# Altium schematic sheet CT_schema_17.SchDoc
size 742 x 377 mm
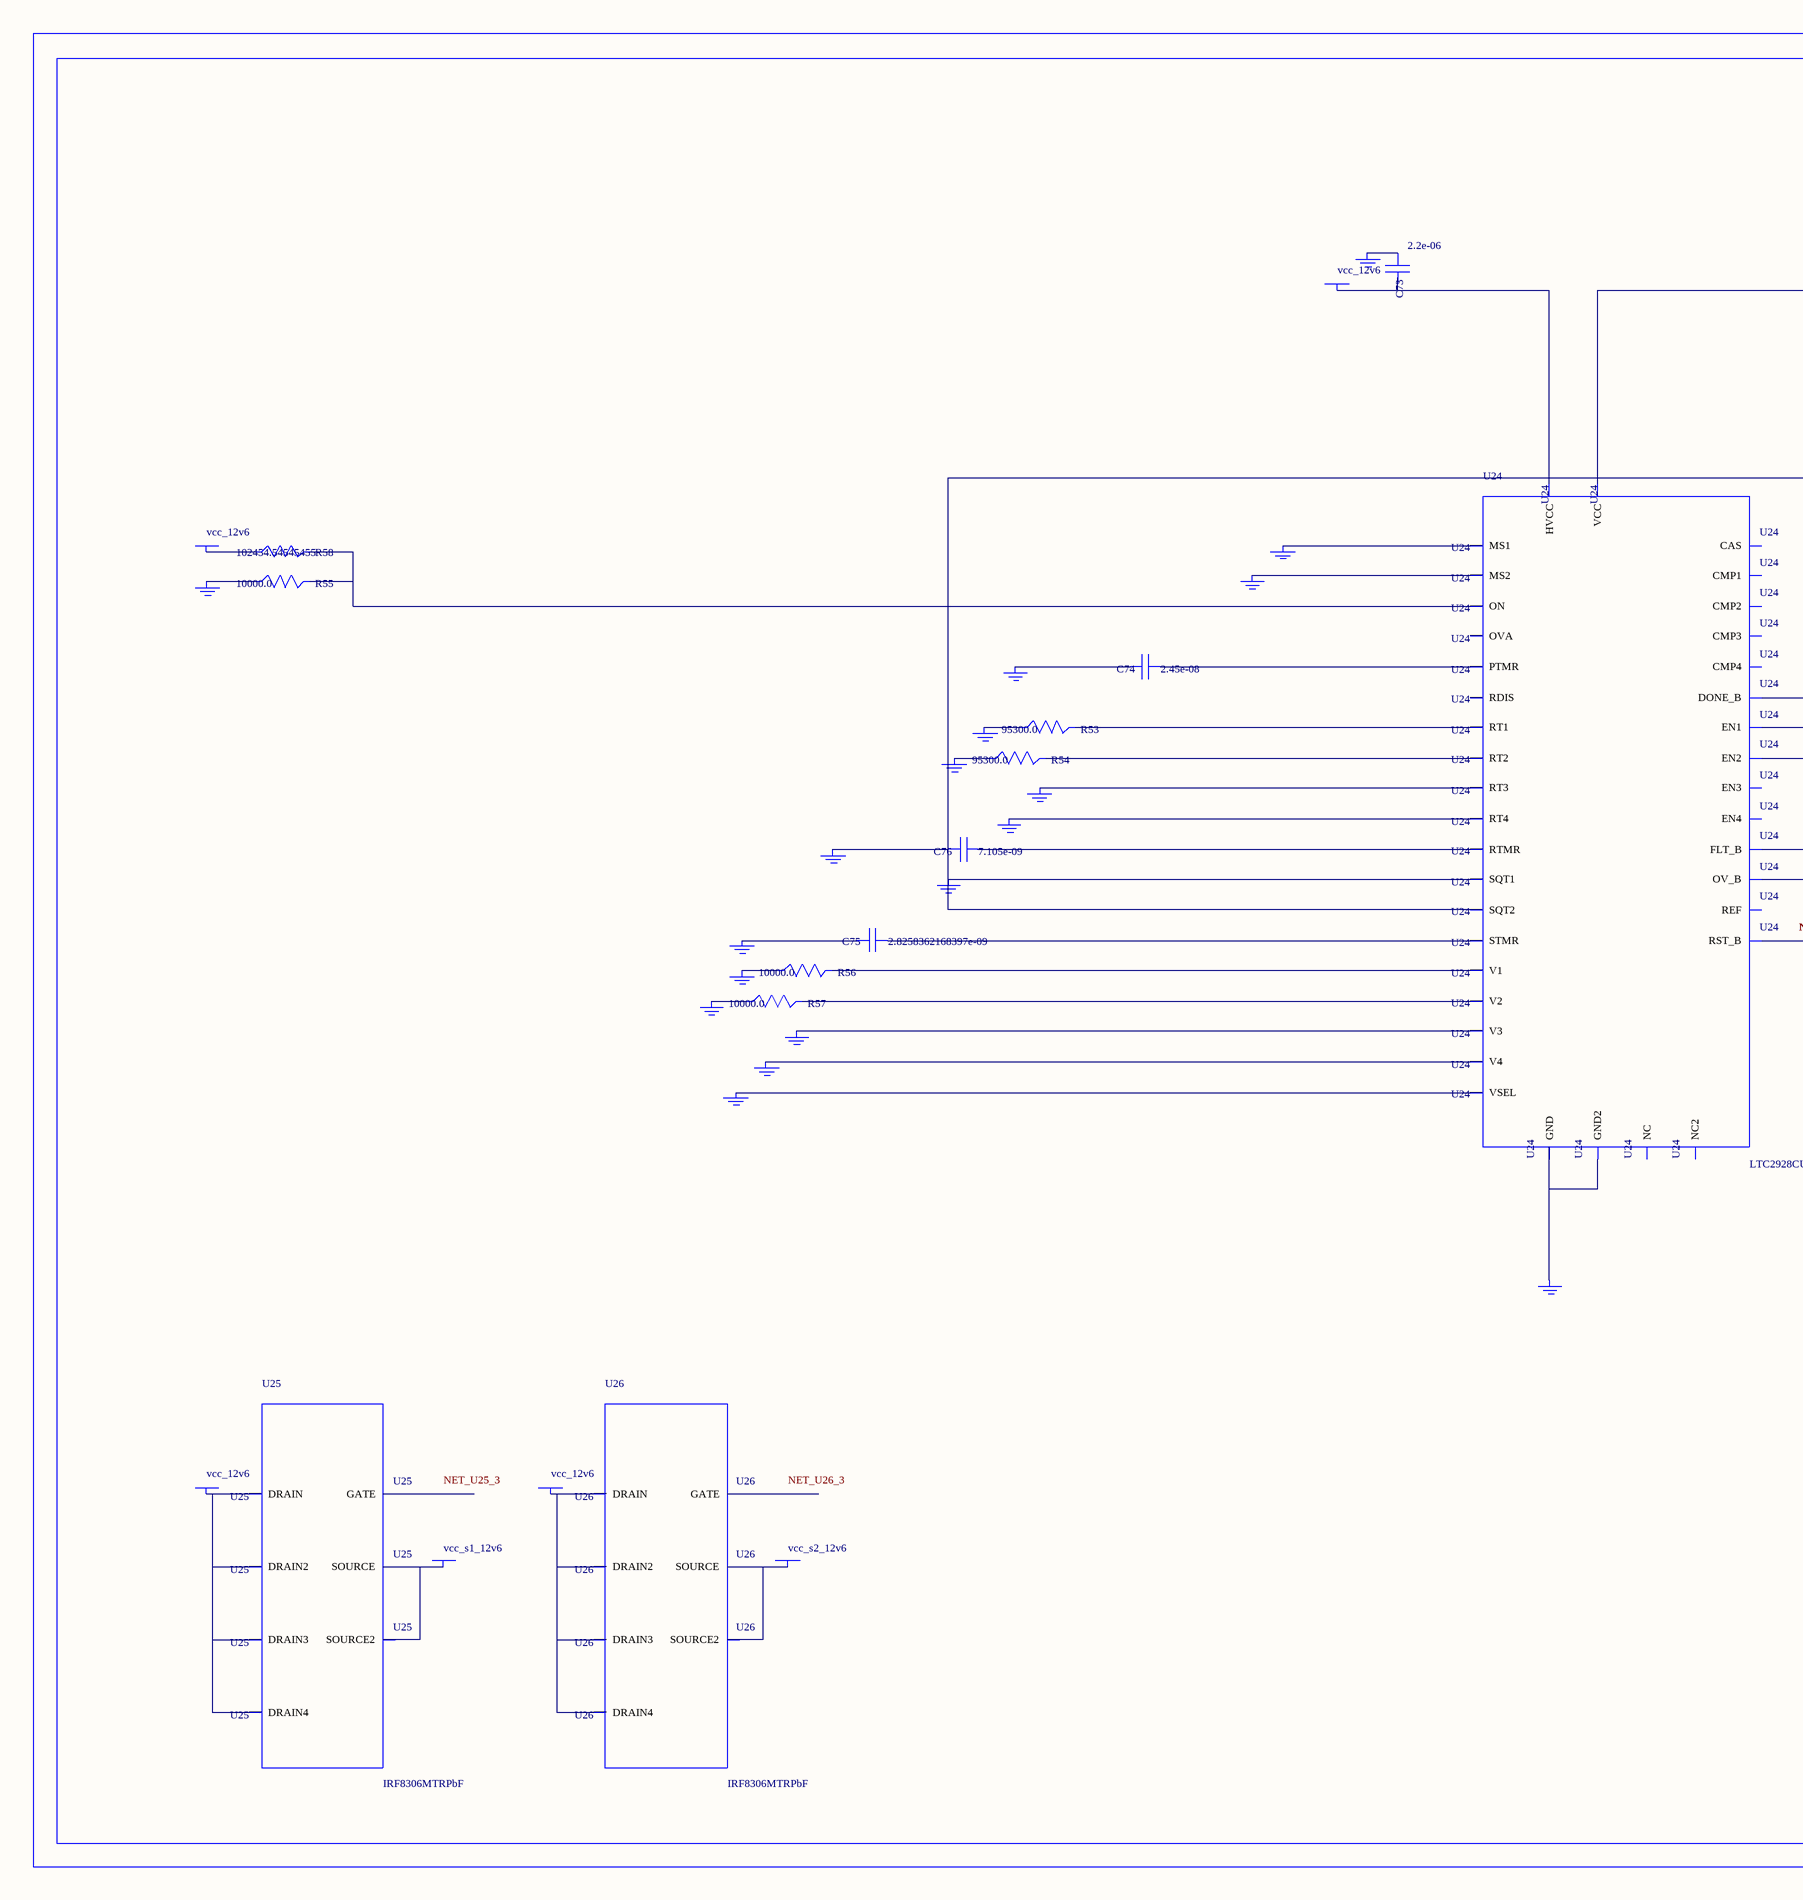
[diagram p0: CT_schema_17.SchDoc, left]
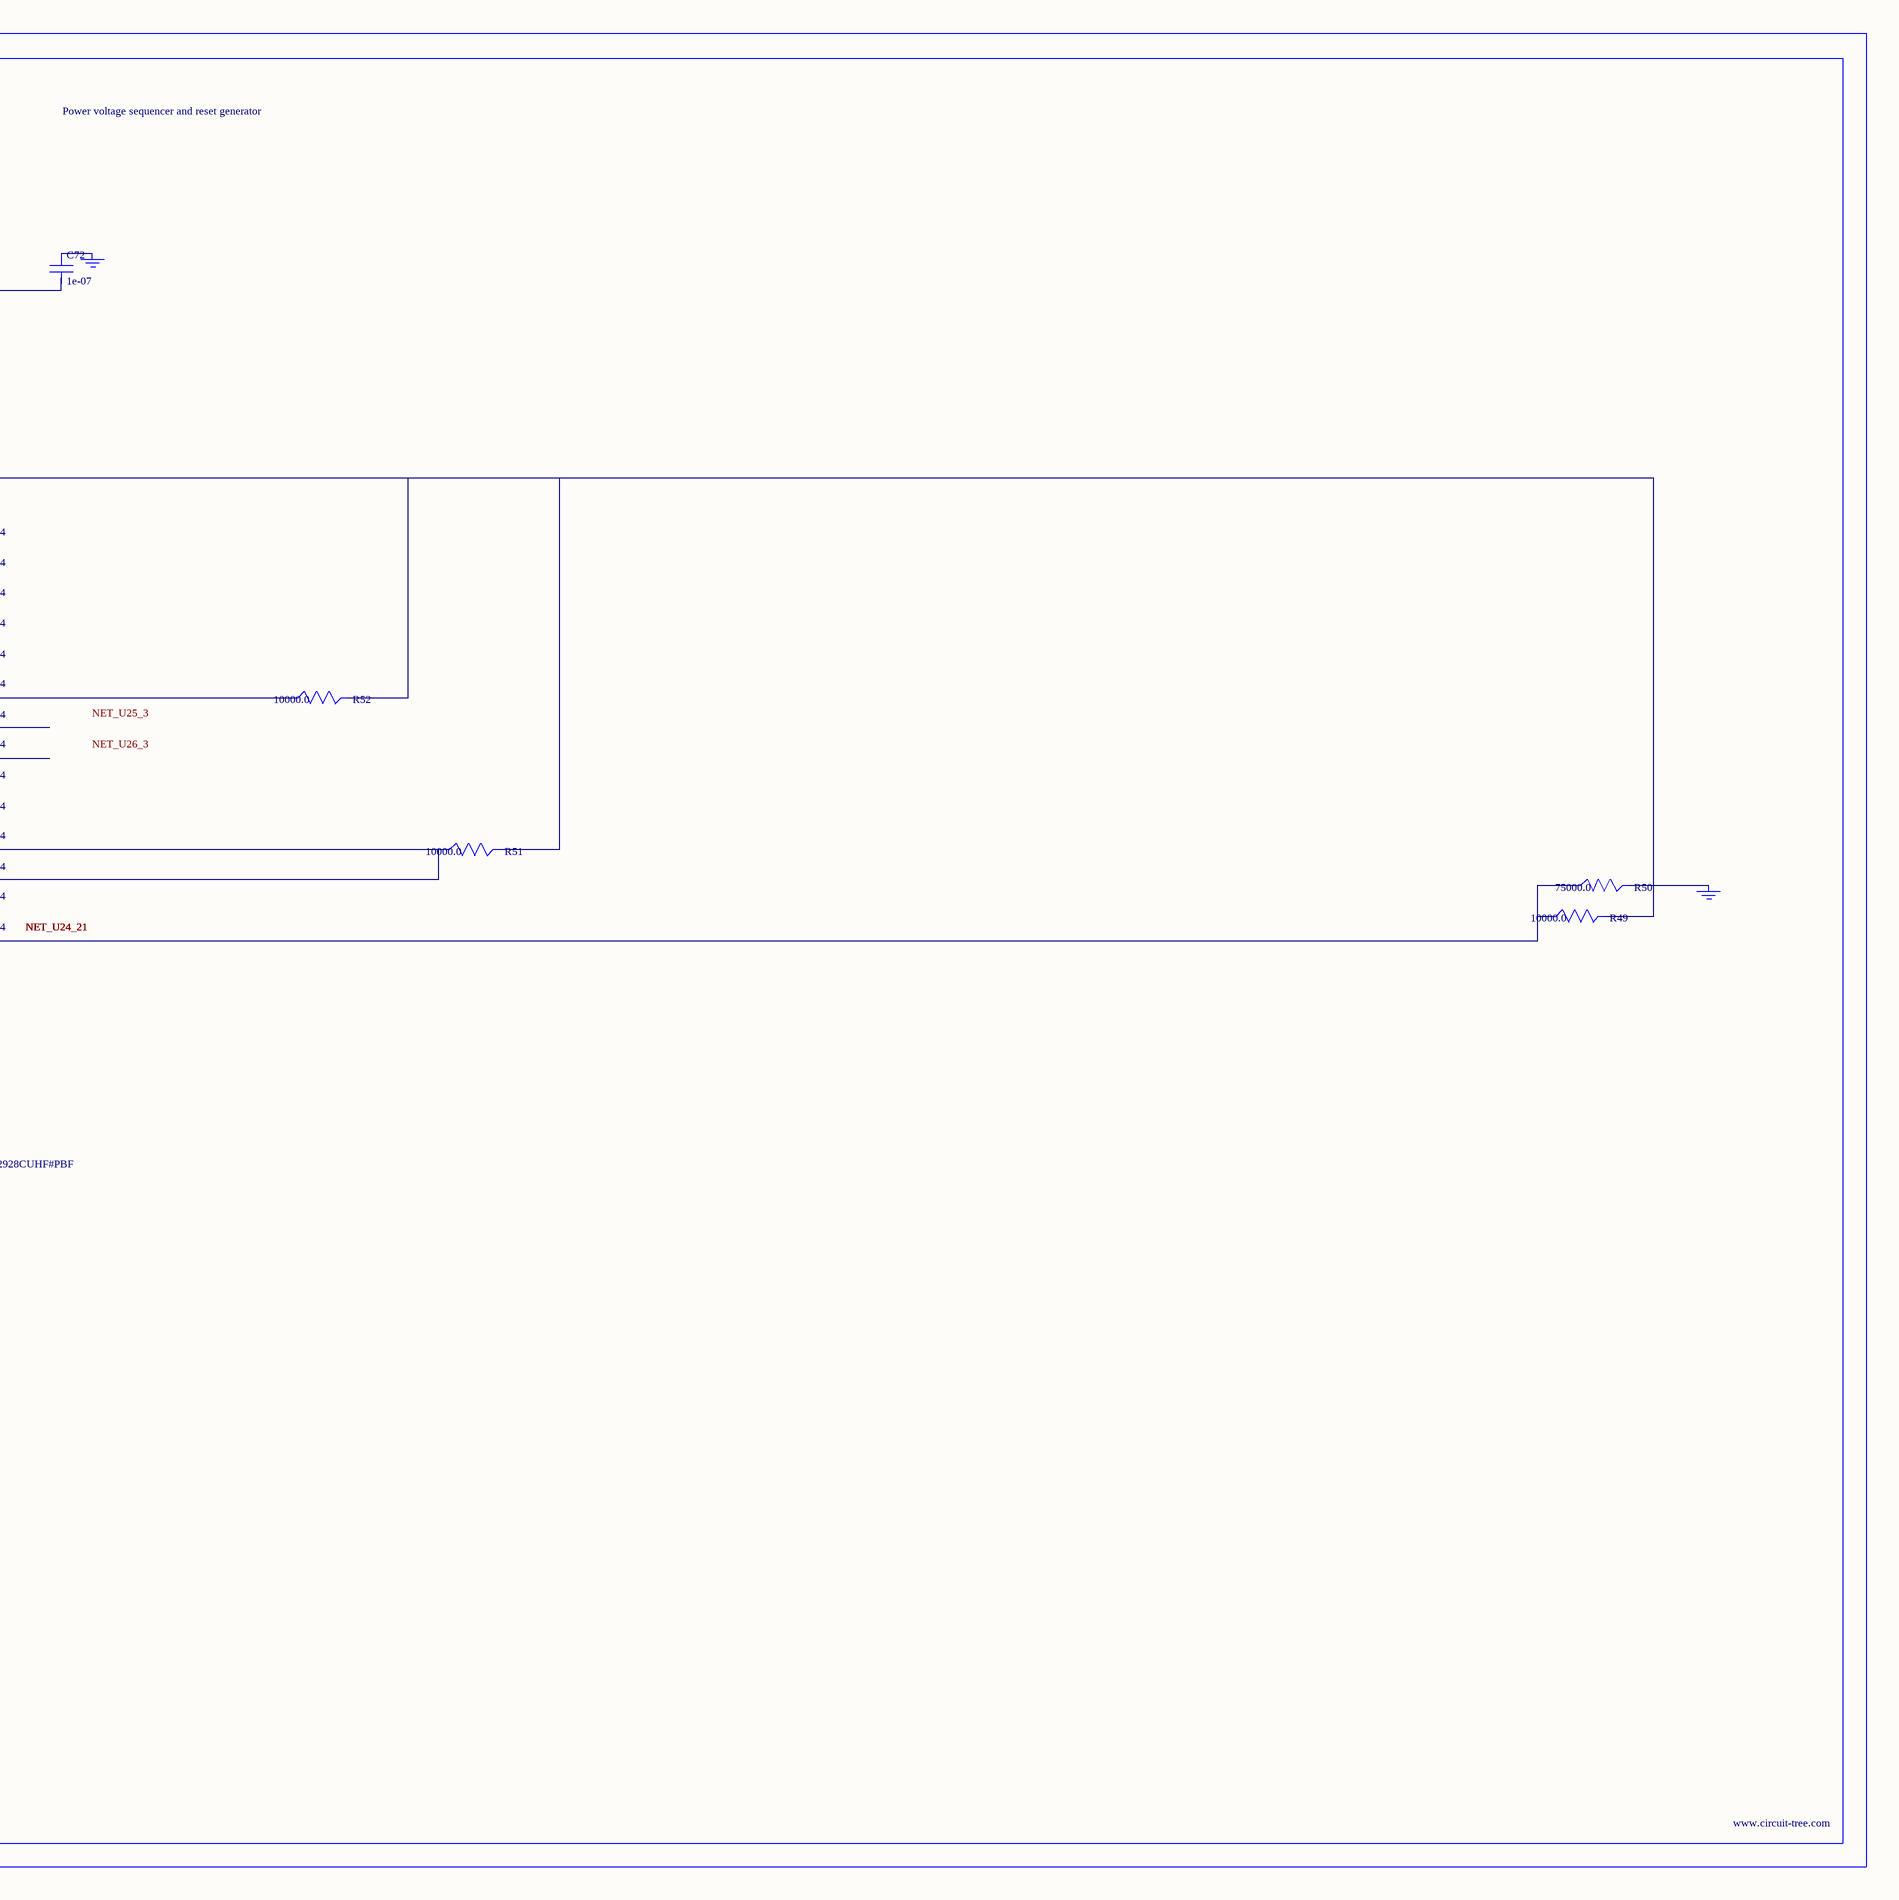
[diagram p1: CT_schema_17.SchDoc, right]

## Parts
BORDER16  (no value)
C72  1e-07  [C0402]
C73  2.2e-06  [C0603]
C74  2.45e-08  [R0603]
C75  2.8258362168397e-09  [R0603]
C76  7.105e-09  [R0603]
GND_INSTANCE_16_0  (no value)
GND_INSTANCE_16_1  (no value)
GND_INSTANCE_16_2  (no value)
GND_INSTANCE_16_3  (no value)
GND_INSTANCE_16_4  (no value)
GND_INSTANCE_16_5  (no value)
GND_INSTANCE_16_6  (no value)
GND_INSTANCE_16_7  (no value)
GND_INSTANCE_16_8  (no value)
GND_INSTANCE_16_9  (no value)
GND_INSTANCE_16_10  (no value)
GND_INSTANCE_16_11  (no value)
GND_INSTANCE_16_12  (no value)
GND_INSTANCE_16_13  (no value)
GND_INSTANCE_16_14  (no value)
GND_INSTANCE_16_15  (no value)
GND_INSTANCE_16_16  (no value)
GND_INSTANCE_16_17  (no value)
GND_INSTANCE_16_18  (no value)
GND_INSTANCE_16_19  (no value)
POWER_INSTANCE_16_0  vcc_12v6
POWER_INSTANCE_16_1  vcc_12v6
POWER_INSTANCE_16_2  vcc_12v6
POWER_INSTANCE_16_3  vcc_s1_12v6
POWER_INSTANCE_16_4  vcc_12v6
POWER_INSTANCE_16_5  vcc_s2_12v6
R49  10000.0  [R0603]
R50  75000.0  [R0603]
R51  10000.0  [R0603]
R52  10000.0  [R0603]
R53  95300.0  [R0603]
R54  95300.0  [R0603]
R55  10000.0  [R0603]
R56  10000.0  [R0603]
R57  10000.0  [R0603]
R58  102454.54545455  [R0603]
U24  LTC2928CUHF#PBF  [QFN-38_UHF]
U25  IRF8306MTRPbF  [IRF8306MTRPBF]
U26  IRF8306MTRPbF  [IRF8306MTRPBF]

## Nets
NetC72_1: C72.1 GND_INSTANCE_16_10.0(GND)
NetC72_2: C72.2 C76.2 GND_INSTANCE_16_5.0(GND) GND_INSTANCE_16_15.0(GND) R49.2 R51.2 R52.2 U24.10(SQT1) U24.11(SQT2) U24.22(VCC)
NetC73_1: C73.1 GND_INSTANCE_16_11.0(GND)
NetC73_2: C73.2 POWER_INSTANCE_16_1.0(PWR) U24.23(HVCC)
NetC74_1: C74.1 U24.27(PTMR)
NetC74_2: C74.2 GND_INSTANCE_16_14.0(GND)
NetC75_1: C75.1 U24.26(STMR)
NetC75_2: C75.2 GND_INSTANCE_16_13.0(GND)
NetC76_1: C76.1 U24.28(RTMR)
NetGND_INSTANCE_16_0_0: GND_INSTANCE_16_0.0(GND) R56.1
NetGND_INSTANCE_16_1_0: GND_INSTANCE_16_1.0(GND) R53.1
NetGND_INSTANCE_16_2_0: GND_INSTANCE_16_2.0(GND) R54.1
NetGND_INSTANCE_16_3_0: GND_INSTANCE_16_3.0(GND) U24.8(RT3)
NetGND_INSTANCE_16_4_0: GND_INSTANCE_16_4.0(GND) U24.9(RT4)
NetGND_INSTANCE_16_6_0: GND_INSTANCE_16_6.0(GND) U24.12(MS1)
NetGND_INSTANCE_16_7_0: GND_INSTANCE_16_7.0(GND) U24.13(MS2)
NetGND_INSTANCE_16_8_0: GND_INSTANCE_16_8.0(GND) R55.1
NetGND_INSTANCE_16_9_0: GND_INSTANCE_16_9.0(GND) R50.2
NetGND_INSTANCE_16_12_0: GND_INSTANCE_16_12.0(GND) U24.25(VSEL)
NetGND_INSTANCE_16_16_0: GND_INSTANCE_16_16.0(GND) U24.30(V4)
NetGND_INSTANCE_16_17_0: GND_INSTANCE_16_17.0(GND) U24.32(V3)
NetGND_INSTANCE_16_18_0: GND_INSTANCE_16_18.0(GND) R57.1
NetGND_INSTANCE_16_19_0: GND_INSTANCE_16_19.0(GND) U24.24(GND) U24.39(GND2)
NetPOWER_INSTANCE_16_0_0: POWER_INSTANCE_16_0.0(PWR) R58.1
NetPOWER_INSTANCE_16_2_0: POWER_INSTANCE_16_2.0(PWR) U25.1(DRAIN) U25.2(DRAIN2) U25.6(DRAIN3) U25.7(DRAIN4)
NetPOWER_INSTANCE_16_3_0: POWER_INSTANCE_16_3.0(PWR) U25.4(SOURCE) U25.5(SOURCE2)
NetPOWER_INSTANCE_16_4_0: POWER_INSTANCE_16_4.0(PWR) U26.1(DRAIN) U26.2(DRAIN2) U26.6(DRAIN3) U26.7(DRAIN4)
NetPOWER_INSTANCE_16_5_0: POWER_INSTANCE_16_5.0(PWR) U26.4(SOURCE) U26.5(SOURCE2)
NetR49_1: R49.1 R50.1 U24.21(RST_B)
NetR51_1: R51.1 U24.19(FLT_B) U24.20(OV_B)
NetR52_1: R52.1 U24.18(DONE_B)
NetR53_2: R53.2 U24.6(RT1)
NetR54_2: R54.2 U24.7(RT2)
NetR55_2: R55.2 R58.2 U24.16(ON)
NetR56_2: R56.2 U24.3(V1)
NetR57_2: R57.2 U24.38(V2)

Not connected (* = marked no-connect by the designer): U24 1(OVA) 2(EN1) 4(NC) 5(REF) 14(RDIS) 15(CAS) 17(NC2) 29(EN4) 31(EN3) 33(CMP3) 34(CMP4) 35(CMP1) 36(CMP2) 37(EN2); U25 3(GATE); U26 3(GATE)

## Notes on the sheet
- Labels drawn without touching a wire or pin: NET_U25_3, NET_U26_3

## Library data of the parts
BORDER16 = BORDER_PAGE16
C72 = C0402C104K3RACTU
C73 = GRM188R61H225KE1115D
C74 = C74
C75 = C75
C76 = C76
GND_INSTANCE_16_0-GND_INSTANCE_16_19 = GND
POWER_INSTANCE_16_0-POWER_INSTANCE_16_5 = PWR
R49 R51 R52 R55-R57 = RC0603JR-0710KL
R50 = RC0603JR-0775KL
R53 R54 = RC0603FR-0795K3L
R58 = R58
